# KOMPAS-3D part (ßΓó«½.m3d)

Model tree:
1. Эскиз:1
2. Операция вращения:1
     Угол 1 = 360
3. Эскиз:2
4. Отверстие:1
5. Эскиз:3
6. Операция выдавливания:1
     Расстояние 1 = 0.5
7. Эскиз:4
8. Операция выдавливания:2
     Расстояние 1 = 2
9. Эскиз:5
10. Операция выдавливания:3
     Расстояние 1 = 1; Расстояние 2 = 1
11. Скругление:1
     Радиус = 0.1
12. Скругление:2
     Радиус = 0.3
13. Эскиз:6
14. Операция выдавливания:4
     Расстояние 1 = 0.01
15. Массив по концентрической сетке:1  (with: Операция выдавливания:4)  (labels: Экземпляр ( 1, 1 ); Экземпляр ( 1, 2 ); Экземпляр ( 1, 3 ); Экземпляр ( 1, 4 ))
     N 2 = 4; Шаг 2 = 360; Номер 2 = 1
16. Эскиз:7
17. Операция выдавливания:5
     Расстояние 1 = 0.5
18. Массив по концентрической сетке:2  (with: Операция выдавливания:5)  (labels: Экземпляр ( 1, 1 ); Экземпляр ( 1, 2 ); Экземпляр ( 1, 3 ); Экземпляр ( 1, 4 ))
     N 2 = 4; Шаг 2 = 360; Номер 2 = 1
19. Эскиз:8
20. Операция выдавливания:6
     Расстояние 1 = 0.3; Расстояние 2 = 0.3
21. Массив по концентрической сетке:3  (with: Операция выдавливания:6)  (labels: Экземпляр ( 1, 1 ); Экземпляр ( 1, 2 ); Экземпляр ( 1, 3 ); Экземпляр ( 1, 4 ))
     N 2 = 8; Шаг 2 = 360; Номер 2 = 1

Referenced files in C:\Program Files\ASCON\KOMPAS-3D V13 Home\Sys\: holelib.lfr
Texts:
  stalker61
  Сплав АЛ8  ГОСТ 1583-93
  Отверстие 01
  (вариант 1)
